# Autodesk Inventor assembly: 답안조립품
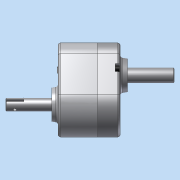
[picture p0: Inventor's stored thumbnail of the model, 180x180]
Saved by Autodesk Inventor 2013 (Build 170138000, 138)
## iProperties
Created: 2014-12
Part Number: 답안조립품
Document SubType Name: Assembly
Designer: WINDOWS7
Author: WINDOWS7
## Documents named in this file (14)
- C:\Users\WINDOWS7\Desktop\441209V1025\답안조립품.iam
- C:\Users\WINDOWS7\Desktop\441209V1025\1-본체.ipt
- C:\Users\WINDOWS7\Desktop\441209V1025\커버.ipt
- C:\Users\WINDOWS7\Desktop\441209V1025\메인축.ipt
- C:\Users\WINDOWS7\Desktop\441209V1025\멈춤링.ipt
- C:\Users\WINDOWS7\Desktop\441209V1025\베어링- 6203.ipt
- C:\Users\WINDOWS7\Desktop\441209V1025\오일시일-D-17.ipt
- C:\Users\WINDOWS7\Desktop\441209V1025\서브축.ipt
- C:\Users\WINDOWS7\Desktop\441209V1025\베어링- 6202.ipt
- C:\Users\WINDOWS7\Desktop\441209V1025\오일시일-D-15.ipt
- C:\Users\WINDOWS7\Desktop\441209V1025\서브기어.ipt
- C:\Users\WINDOWS7\Desktop\441209V1025\키5x5.ipt
- C:\Users\WINDOWS7\Desktop\441209V1025\메인기어.ipt
- C:\Users\WINDOWS7\Desktop\441209V1025\M 5 x 35.ipt
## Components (16 placed, 7 different names)
1. 1-본체:1
2. KS B 2023 6203 - 17 x 40 x 12:1
3. KS B 2804 D D - 17 30 8:1
4. KS B 2023 6202 - 15 x 35 x 11:1
5. KS B 2023 6202 - 15 x 35 x 11:2
6. KS B 2804 D D - 15 30 7:1
7. KS B 2804 D D - 15 30 7:2
8. KS B 2023 6203 - 17 x 40 x 12:2
9. KS B 2023 6203 - 17 x 40 x 12:3
10. KS B 1336 17 x 1:2
11. KS B 1336 17 x 1:3
12. KS B 1336 17 x 1:4
13. KS B 2023 6203 - 17 x 40 x 12:4
14. KS B 1003 - 미터 M 5 x 35:1
15. KS B 1003 - 미터 M 5 x 35:2
16. KS B 1003 - 미터 M 5 x 35:3
